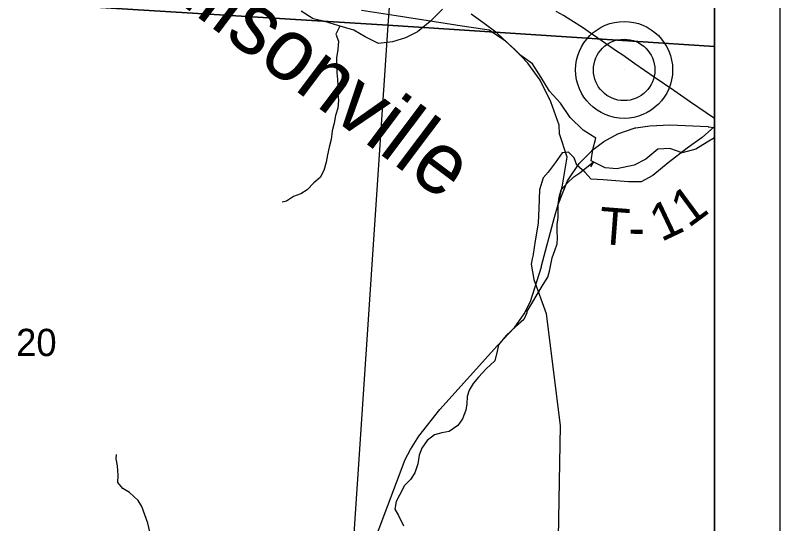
# Model space of a CAD drawing. Extents: x 0 to 34, y 0 to 22.
# Drawn here: x 7.827 to 9, y 16.547 to 17.328 of the extents above; entities that cross this region are included whole.
import ezdxf

# ---------------------------------------------------------------- set-up
doc = ezdxf.new("R2010")
doc.units = 0
for name, color, linetype in [('GM_X_Minor_River', 7, 'Continuous'), ('GM_X_Minor_River_Text', 7, 'Continuous'), ('GM_X_Rail_Line', 7, 'Continuous'), ('GM_X_Section', 7, 'Continuous'), ('GM_X_Section_Text', 7, 'Continuous'), ('GM_X_State_Route', 7, 'Continuous'), ('GM_X_Township_Road', 7, 'Continuous'), ('GM_X_Township_Road_Text', 7, 'Continuous'), ('GM_X_Unincorporated', 7, 'Continuous'), ('GM_X_Unincorporated_Location', 7, 'Continuous'), ('SH_Cut_Line', 7, 'Continuous'), ('SH_Data', 7, 'Continuous')]:
    doc.layers.add(name, color=color, linetype=linetype)

msp = doc.modelspace()

# ---------------------------------------------------------------- linework, layer by layer
at = {"layer": 'GM_X_Minor_River'}
for points in [[(8.4826, 17.3374), (8.4635, 17.3185), (8.4441, 17.3026), (8.4254, 17.2932), (8.4057, 17.2869), (8.384, 17.2847), (8.3636, 17.2947), (8.3462, 17.305), (8.3216, 17.312), (8.3016, 17.3182), (8.2838, 17.3224), (8.2657, 17.3343)], [(8.9, 17.1399), (8.8889, 17.1329), (8.8714, 17.1223), (8.8501, 17.1167), (8.8316, 17.1233), (8.813, 17.1222), (8.7943, 17.1072), (8.7764, 17.0978), (8.7502, 17.0922), (8.732, 17.0938), (8.7108, 17.1046), (8.7132, 17.122), (8.7179, 17.1391), (8.6983, 17.1513), (8.6783, 17.1708), (8.6637, 17.1929), (8.6467, 17.2116), (8.634, 17.2325), (8.6208, 17.2531), (8.6027, 17.2661), (8.5843, 17.2833), (8.5662, 17.3005), (8.5443, 17.3169), (8.5265, 17.3295)], [(8.3246, 17.3111), (8.3188, 17.2989), (8.3229, 17.2883), (8.322, 17.2754), (8.3197, 17.2625), (8.3196, 17.2511), (8.3203, 17.2394), (8.3214, 17.2295), (8.322, 17.22), (8.322, 17.2075), (8.3226, 17.1972), (8.3218, 17.1855), (8.3183, 17.1741), (8.316, 17.162), (8.3129, 17.1506), (8.3116, 17.137), (8.3085, 17.1252), (8.3058, 17.1135), (8.3038, 17.1021), (8.3003, 17.0896), (8.2946, 17.0787), (8.2847, 17.0704), (8.2747, 17.0598), (8.2648, 17.0535), (8.2538, 17.0494), (8.2428, 17.0426), (8.2364, 17.0411)], [(8.6119, 16.8726), (8.6369, 16.9143), (8.6442, 16.9257), (8.6465, 16.9351), (8.6489, 16.945), (8.6508, 16.9552), (8.6547, 16.9666), (8.6586, 16.9768), (8.659, 16.9863), (8.6583, 16.9965), (8.6584, 17.0064), (8.66, 17.0174), (8.6597, 17.0272), (8.6601, 17.0375), (8.6617, 17.0485), (8.6648, 17.0598), (8.6744, 17.0708), (8.6839, 17.0798), (8.6934, 17.0862), (8.7142, 17.1028), (8.7098, 17.0952)], [(8.6119, 16.8726), (8.6117, 16.8708), (8.6075, 16.8605), (8.5943, 16.8495), (8.5803, 16.8362), (8.5686, 16.8218), (8.5663, 16.8123), (8.5629, 16.7975), (8.5493, 16.785), (8.5376, 16.7721), (8.5296, 16.7623), (8.5236, 16.7524), (8.5205, 16.7425), (8.5198, 16.7312), (8.5183, 16.7213), (8.5133, 16.708), (8.5058, 16.6978), (8.4929, 16.6887), (8.4816, 16.6868), (8.4699, 16.6837), (8.4589, 16.675), (8.4506, 16.6632), (8.4464, 16.6522), (8.4445, 16.6393), (8.44, 16.6253), (8.4332, 16.6151), (8.4241, 16.6056), (8.4166, 16.5912), (8.4113, 16.5813), (8.4094, 16.5695), (8.415, 16.5597), (8.4226, 16.5438)], [(8.0151, 16.5829), (8.0022, 16.5952), (7.992, 16.601), (7.9841, 16.6105), (7.9845, 16.6218), (7.9834, 16.6363), (7.9816, 16.6469), (7.982, 16.6533)], [(8.0347, 16.528), (8.0302, 16.5481), (8.0257, 16.5606), (8.0208, 16.5735), (8.0151, 16.5829)]]:
    msp.add_lwpolyline(points, dxfattribs=at)
at = {"layer": 'GM_X_Rail_Line'}
for points in [[(8.66, 17.0374), (8.6666, 17.0669), (8.6738, 17.1102), (8.6618, 17.1456), (8.6614, 17.159), (8.6485, 17.1952), (8.6323, 17.2282), (8.6133, 17.2544), (8.5932, 17.2755), (8.579, 17.288), (8.5541, 17.305), (8.5335, 17.3079), (8.5191, 17.3101), (8.4114, 17.3271), (8.3583, 17.3351)], [(8.66, 17.0374), (8.6744, 17.0736), (8.6752, 17.0752), (8.6921, 17.1001), (8.7114, 17.1195), (8.7114, 17.1203), (8.7299, 17.1339), (8.7517, 17.146), (8.7782, 17.1549), (8.779, 17.1549), (8.8007, 17.1581), (8.8313, 17.1597), (8.89, 17.1573), (8.89, 17.1565), (8.9, 17.1554)], [(8.372, 16.5047), (8.425, 16.6456), (8.4331, 16.6609), (8.4463, 16.6817), (8.4782, 16.7226), (8.5667, 16.8209), (8.5932, 16.8491), (8.6077, 16.8692), (8.6173, 16.8885), (8.6342, 16.9416), (8.6342, 16.9432), (8.6543, 17.0181), (8.66, 17.0374)]]:
    msp.add_lwpolyline(points, dxfattribs=at)
at = {"layer": 'GM_X_Section'}
for points in [[(7.4583, 18.399), (8.4739, 18.3269), (8.3983, 17.3128), (7.3907, 17.3751)], [(7.3907, 17.3751), (8.3983, 17.3128), (8.3308, 16.3019), (7.3221, 16.3607)]]:
    msp.add_lwpolyline(points, close=True, dxfattribs=at)
at = {"layer": 'GM_X_State_Route'}
msp.add_lwpolyline([(8.9, 17.1694), (8.8872, 17.1783), (8.8632, 17.1945), (8.8377, 17.2122), (8.8074, 17.2328), (8.7776, 17.2533), (8.7591, 17.2664), (8.7493, 17.2727), (8.7274, 17.2881), (8.7109, 17.2995), (8.6972, 17.3089), (8.6792, 17.3205), (8.6682, 17.3274), (8.6569, 17.3335)], dxfattribs=at)
at = {"layer": 'GM_X_Township_Road'}
for points in [[(8.9, 17.157), (8.881, 17.1401), (8.8578, 17.1236), (8.8287, 17.1014), (8.8055, 17.082), (8.7871, 17.0724), (8.7677, 17.0724), (8.729, 17.0753), (8.7106, 17.0762), (8.701, 17.0869), (8.6884, 17.0975), (8.6845, 17.1091), (8.6758, 17.1179), (8.6661, 17.1169), (8.6555, 17.1014), (8.6448, 17.0869), (8.6371, 17.0782), (8.6313, 17.0598), (8.6303, 17.0317), (8.6293, 17.0085), (8.6245, 16.9814), (8.6216, 16.9611), (8.6214, 16.96)], [(8.6214, 16.96), (8.6202, 16.9539), (8.6187, 16.9456), (8.6226, 16.9224), (8.6415, 16.8702), (8.6631, 16.6973), (8.66, 16.5258), (8.6662, 16.393), (8.6616, 16.2293), (8.6656, 16.1163)]]:
    msp.add_lwpolyline(points, dxfattribs=at)
at = {"layer": 'GM_X_Township_Road_Text'}
for points in [[(8.9, 17.2802), (8.9, 18.2954), (8.4739, 18.3269), (8.3983, 17.3128)], [(8.9, 16.2701), (8.9, 17.2802), (8.3983, 17.3128), (8.3308, 16.3019)]]:
    msp.add_lwpolyline(points, close=True, dxfattribs=at)
at = {"layer": 'GM_X_Unincorporated'}
msp.add_lwpolyline([(8.9, 14.2264), (8.9, 20.3234), (8.6245, 20.3436), (7.6038, 20.4229), (7.3955, 20.4364), (6.962, 20.4644), (6.8381, 20.4724), (6.7584, 20.4776), (6.6718, 20.4832), (6.6484, 20.4847), (4.3099, 20.6409), (3.8602, 20.6728), (3.5651, 20.6937), (3.5462, 20.4144), (3.5457, 20.4056), (3.5456, 20.4047), (3.5099, 19.8769)], dxfattribs=at)
for radius in [0.0744, 0.0472]:
    msp.add_circle((8.7612, 17.244), radius, dxfattribs=at)
at = {"layer": 'GM_X_Unincorporated_Location'}
msp.add_line((8.7612, 17.244), (8.7612, 17.244), dxfattribs=at)
at = {"layer": 'SH_Cut_Line'}
msp.add_lwpolyline([(8.9, 14.1), (8.9, 20.9), (6.769, 20.9), (6.6568, 20.5136), (6.6484, 20.4847), (4.3099, 20.6409), (3.8602, 20.6728), (3.5651, 20.6937), (3.5462, 20.4144), (3.5457, 20.4056), (3.5456, 20.4047), (3.5099, 19.8769), (3.4599, 19.1361), (3.4595, 19.1305), (3.4011, 18.2653), (3.709, 17.484), (3.7367, 17.4136), (3.972, 16.8916), (4.0882, 16.6114), (4.2937, 16.1161)], dxfattribs=at)
at = {"layer": 'SH_Data'}
for p, q in [((9, 21), (9, 14)), ((8.9, 20.9), (8.9, 14.1))]:
    msp.add_line(p, q, dxfattribs=at)

# ---------------------------------------------------------------- texts
at = {"layer": 'GM_X_Minor_River_Text'}
msp.add_text('Ellisonville', height=0.094688, rotation=323.0648, dxfattribs=at).set_placement((8.0111, 17.3967))
at = {"layer": 'GM_X_Section_Text'}
msp.add_text('20', height=0.04186, rotation=0, dxfattribs=at).set_placement((7.8279, 16.8046))
at = {"layer": 'GM_X_Township_Road_Text'}
for s, rotation, p in [('1', 36.3832, (8.86, 17.0005)), ('1', 25.3151, (8.8181, 16.9794)), ('T', 355.6264, (8.7211, 16.9771)), ('-', 359.3496, (8.7675, 16.9737))]:
    msp.add_text(s, height=0.0568, rotation=rotation, dxfattribs=at).set_placement(p)

doc.saveas('drawing.dxf')
